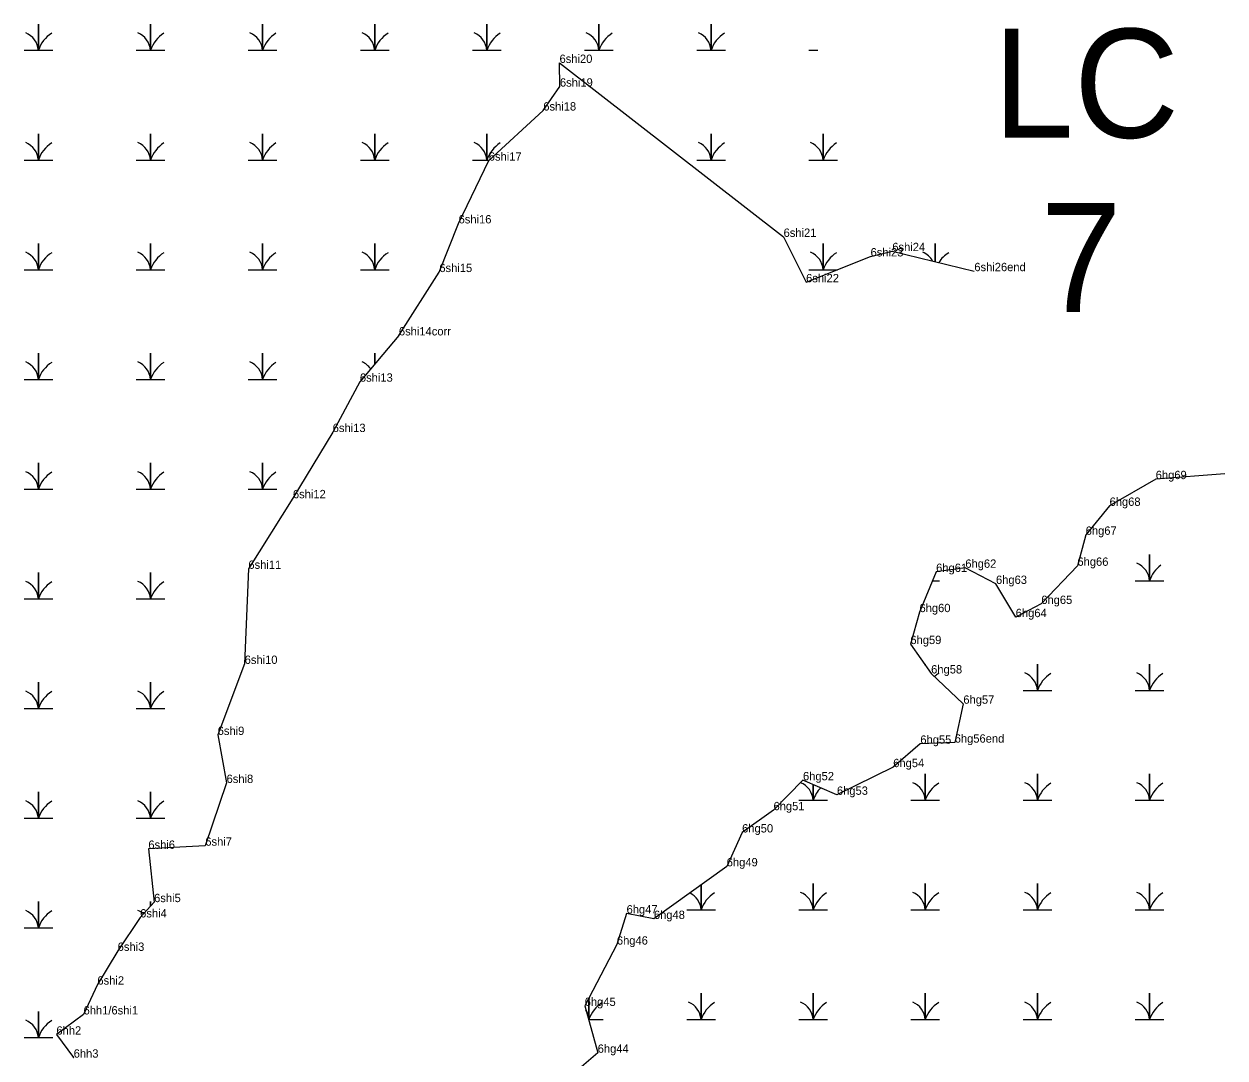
# Model space of a CAD drawing. Extents: x 2072529 to 2268796, y 436423 to 470406.
# Drawn here: x 2148024 to 2148744, y 442728 to 443348 of the extents above; entities that cross this region are included whole.
import ezdxf

# ---------------------------------------------------------------- set-up
doc = ezdxf.new("R2010")
doc.units = 0
for name, color, linetype in [('Default', 7, 'Continuous'), ('Exist Environmental Wetland Boundary Cogo Comment', 7, 'Continuous'), ('Exist Environmental Wetland Boundary Cogo Point CELL', 7, 'Continuous'), ('Exist Hydro Jurisdictional Stream or Body of Water NEU Mitigable Cogo Comment', 7, 'Continuous'), ('Old_Level_20', 7, 'Continuous'), ('Old_Level_52', 7, 'Continuous')]:
    doc.layers.add(name, color=color, linetype=linetype)

msp = doc.modelspace()

# ---------------------------------------------------------------- linework, layer by layer
at = {"layer": 'Exist Environmental Wetland Boundary Cogo Point CELL'}
for points in [[(2148023.58, 443332.03), (2148032.18, 443332.03), (2148032.18, 443347.81), (2148032.18, 443332.03), (2148040.78, 443332.03)], [(2148090.83, 443332.03), (2148099.43, 443332.03), (2148099.43, 443347.81), (2148099.43, 443332.03), (2148108.03, 443332.03)], [(2148158.08, 443332.03), (2148166.68, 443332.03), (2148166.68, 443347.81), (2148166.68, 443332.03), (2148175.28, 443332.03)], [(2148225.33, 443332.03), (2148233.93, 443332.03), (2148233.93, 443347.81), (2148233.93, 443332.03), (2148242.53, 443332.03)], [(2148292.58, 443332.03), (2148301.18, 443332.03), (2148301.18, 443347.81), (2148301.18, 443332.03), (2148309.78, 443332.03)], [(2148359.83, 443332.03), (2148368.43, 443332.03), (2148368.43, 443347.81), (2148368.43, 443332.03), (2148377.03, 443332.03)], [(2148427.08, 443332.03), (2148435.68, 443332.03), (2148435.68, 443347.81), (2148435.68, 443332.03), (2148444.28, 443332.03)], [(2148494.33, 443332.03), (2148499.78, 443332.03)], [(2148023.58, 443266.23), (2148032.18, 443266.23), (2148032.18, 443282.01), (2148032.18, 443266.23), (2148040.78, 443266.23)], [(2148090.83, 443266.23), (2148099.43, 443266.23), (2148099.43, 443282.01), (2148099.43, 443266.23), (2148108.03, 443266.23)], [(2148158.08, 443266.23), (2148166.68, 443266.23), (2148166.68, 443282.01), (2148166.68, 443266.23), (2148175.28, 443266.23)], [(2148225.33, 443266.23), (2148233.93, 443266.23), (2148233.93, 443282.01), (2148233.93, 443266.23), (2148242.53, 443266.23)], [(2148292.58, 443266.23), (2148301.18, 443266.23), (2148301.18, 443282.01), (2148301.18, 443266.23), (2148302.75, 443266.23)], [(2148427.08, 443266.23), (2148435.68, 443266.23), (2148435.68, 443282.01), (2148435.68, 443266.23), (2148444.28, 443266.23)], [(2148494.33, 443266.23), (2148502.93, 443266.23), (2148502.93, 443282.01), (2148502.93, 443266.23), (2148511.53, 443266.23)], [(2148023.58, 443200.43), (2148032.18, 443200.43), (2148032.18, 443216.21), (2148032.18, 443200.43), (2148040.78, 443200.43)], [(2148090.83, 443200.43), (2148099.43, 443200.43), (2148099.43, 443216.21), (2148099.43, 443200.43), (2148108.03, 443200.43)], [(2148158.08, 443200.43), (2148166.68, 443200.43), (2148166.68, 443216.21), (2148166.68, 443200.43), (2148175.28, 443200.43)], [(2148225.33, 443200.43), (2148233.93, 443200.43), (2148233.93, 443216.21), (2148233.93, 443200.43), (2148242.53, 443200.43)], [(2148494.33, 443200.43), (2148502.93, 443200.43), (2148502.93, 443216.21), (2148502.93, 443200.43), (2148511.47, 443200.43)], [(2148570.18, 443205.29), (2148570.18, 443216.21), (2148570.18, 443205.29)], [(2148023.58, 443134.63), (2148032.18, 443134.63), (2148032.18, 443150.41), (2148032.18, 443134.63), (2148040.78, 443134.63)], [(2148090.83, 443134.63), (2148099.43, 443134.63), (2148099.43, 443150.41), (2148099.43, 443134.63), (2148108.03, 443134.63)], [(2148158.08, 443134.63), (2148166.68, 443134.63), (2148166.68, 443150.41), (2148166.68, 443134.63), (2148175.28, 443134.63)], [(2148233.93, 443143.8), (2148233.93, 443150.41), (2148233.93, 443143.8)], [(2148225.33, 443134.63), (2148226.2, 443134.63)], [(2148023.58, 443068.83), (2148032.18, 443068.83), (2148032.18, 443084.61), (2148032.18, 443068.83), (2148040.78, 443068.83)], [(2148090.83, 443068.83), (2148099.43, 443068.83), (2148099.43, 443084.61), (2148099.43, 443068.83), (2148108.03, 443068.83)], [(2148158.08, 443068.83), (2148166.68, 443068.83), (2148166.68, 443084.61), (2148166.68, 443068.83), (2148175.28, 443068.83)], [(2148690.09, 443013.88), (2148698.69, 443013.88), (2148698.69, 443029.66), (2148698.69, 443013.88), (2148707.29, 443013.88)], [(2148023.58, 443003.03), (2148032.18, 443003.03), (2148032.18, 443018.81), (2148032.18, 443003.03), (2148040.78, 443003.03)], [(2148090.83, 443003.03), (2148099.43, 443003.03), (2148099.43, 443018.81), (2148099.43, 443003.03), (2148108.03, 443003.03)], [(2148568.5, 443013.88), (2148572.79, 443013.88)], [(2148564.19, 442963.22), (2148564.19, 442963.86), (2148564.19, 442963.22)], [(2148622.84, 442948.08), (2148631.44, 442948.08), (2148631.44, 442963.86), (2148631.44, 442948.08), (2148640.04, 442948.08)], [(2148690.09, 442948.08), (2148698.69, 442948.08), (2148698.69, 442963.86), (2148698.69, 442948.08), (2148707.29, 442948.08)], [(2148023.58, 442937.23), (2148032.18, 442937.23), (2148032.18, 442953.01), (2148032.18, 442937.23), (2148040.78, 442937.23)], [(2148090.83, 442937.23), (2148099.43, 442937.23), (2148099.43, 442953.01), (2148099.43, 442937.23), (2148108.03, 442937.23)], [(2148555.59, 442882.28), (2148564.19, 442882.28), (2148564.19, 442898.06), (2148564.19, 442882.28), (2148572.79, 442882.28)], [(2148622.84, 442882.28), (2148631.44, 442882.28), (2148631.44, 442898.06), (2148631.44, 442882.28), (2148640.04, 442882.28)], [(2148690.09, 442882.28), (2148698.69, 442882.28), (2148698.69, 442898.06), (2148698.69, 442882.28), (2148707.29, 442882.28)], [(2148023.58, 442871.43), (2148032.18, 442871.43), (2148032.18, 442887.21), (2148032.18, 442871.43), (2148040.78, 442871.43)], [(2148090.83, 442871.43), (2148099.43, 442871.43), (2148099.43, 442887.21), (2148099.43, 442871.43), (2148108.03, 442871.43)], [(2148488.34, 442882.28), (2148496.94, 442882.28), (2148496.94, 442891.57)], [(2148496.94, 442891.57), (2148496.94, 442882.28), (2148505.54, 442882.28)], [(2148421.09, 442816.48), (2148429.69, 442816.48), (2148429.69, 442831.47)], [(2148429.69, 442831.47), (2148429.69, 442816.48), (2148438.29, 442816.48)], [(2148488.34, 442816.48), (2148496.94, 442816.48), (2148496.94, 442832.26), (2148496.94, 442816.48), (2148505.54, 442816.48)], [(2148555.59, 442816.48), (2148564.19, 442816.48), (2148564.19, 442832.26), (2148564.19, 442816.48), (2148572.79, 442816.48)], [(2148622.84, 442816.48), (2148631.44, 442816.48), (2148631.44, 442832.26), (2148631.44, 442816.48), (2148640.04, 442816.48)], [(2148690.09, 442816.48), (2148698.69, 442816.48), (2148698.69, 442832.26), (2148698.69, 442816.48), (2148707.29, 442816.48)], [(2148023.58, 442805.63), (2148032.18, 442805.63), (2148032.18, 442821.41), (2148032.18, 442805.63), (2148040.78, 442805.63)], [(2148099.43, 442818.71), (2148099.43, 442821.41), (2148099.43, 442818.71)], [(2148362.15, 442750.68), (2148362.44, 442750.68), (2148362.44, 442763.72)], [(2148362.44, 442763.72), (2148362.44, 442750.68), (2148371.04, 442750.68)], [(2148421.09, 442750.68), (2148429.69, 442750.68), (2148429.69, 442766.46), (2148429.69, 442750.68), (2148438.29, 442750.68)], [(2148488.34, 442750.68), (2148496.94, 442750.68), (2148496.94, 442766.46), (2148496.94, 442750.68), (2148505.54, 442750.68)], [(2148555.59, 442750.68), (2148564.19, 442750.68), (2148564.19, 442766.46), (2148564.19, 442750.68), (2148572.79, 442750.68)], [(2148622.84, 442750.68), (2148631.44, 442750.68), (2148631.44, 442766.46), (2148631.44, 442750.68), (2148640.04, 442750.68)], [(2148690.09, 442750.68), (2148698.69, 442750.68), (2148698.69, 442766.46), (2148698.69, 442750.68), (2148707.29, 442750.68)], [(2148023.58, 442739.83), (2148032.18, 442739.83), (2148032.18, 442755.61), (2148032.18, 442739.83), (2148040.78, 442739.83)]]:
    msp.add_lwpolyline(points, dxfattribs=at)
for centre, radius, start, end in [((2148019.91, 443331.14), 12.3, 4.14034, 67.53497), ((2148050.42, 443325.97), 19.22, 122.12745, 161.62219), ((2148087.16, 443331.14), 12.3, 4.14034, 67.53497), ((2148117.67, 443325.97), 19.22, 122.12745, 161.62219), ((2148154.41, 443331.14), 12.3, 4.14034, 67.53497), ((2148184.92, 443325.97), 19.22, 122.12745, 161.62219), ((2148221.66, 443331.14), 12.3, 4.14034, 67.53497), ((2148252.17, 443325.97), 19.22, 122.12745, 161.62219), ((2148288.91, 443331.14), 12.3, 4.14034, 67.53497), ((2148319.42, 443325.97), 19.22, 122.12745, 161.62219), ((2148356.16, 443331.14), 12.3, 4.14034, 67.53497), ((2148386.67, 443325.97), 19.22, 122.12745, 161.62219), ((2148423.41, 443331.14), 12.3, 4.14034, 67.53497), ((2148453.92, 443325.97), 19.22, 122.12745, 161.62219), ((2148019.91, 443265.34), 12.3, 4.14034, 67.53497), ((2148050.42, 443260.17), 19.22, 122.12745, 161.62219), ((2148087.16, 443265.34), 12.3, 4.14034, 67.53497), ((2148117.67, 443260.17), 19.22, 122.12745, 161.62219), ((2148154.41, 443265.34), 12.3, 4.14034, 67.53497), ((2148184.92, 443260.17), 19.22, 122.12745, 161.62219), ((2148221.66, 443265.34), 12.3, 4.14034, 67.53497), ((2148252.17, 443260.17), 19.22, 122.12745, 161.62219), ((2148288.91, 443265.34), 12.3, 4.14034, 67.53497), ((2148319.42, 443260.17), 19.22, 122.12745, 161.62219), ((2148423.41, 443265.34), 12.3, 4.14034, 67.53497), ((2148453.92, 443260.17), 19.22, 122.12745, 161.62219), ((2148490.66, 443265.34), 12.3, 4.14034, 67.53497), ((2148521.17, 443260.17), 19.22, 122.12745, 161.62219), ((2148019.91, 443199.54), 12.3, 4.14034, 67.53497), ((2148050.42, 443194.37), 19.22, 122.12745, 161.62219), ((2148087.16, 443199.54), 12.3, 4.14034, 67.53497), ((2148117.67, 443194.37), 19.22, 122.12745, 161.62219), ((2148154.41, 443199.54), 12.3, 4.14034, 67.53497), ((2148184.92, 443194.37), 19.22, 122.12745, 161.62219), ((2148221.66, 443199.54), 12.3, 4.14034, 67.53497), ((2148252.17, 443194.37), 19.22, 122.12745, 161.62219), ((2148490.66, 443199.54), 12.3, 4.14034, 67.53497), ((2148521.17, 443194.37), 19.22, 122.12745, 161.62219), ((2148557.91, 443199.54), 12.3, 29.96373, 67.53497), ((2148588.42, 443194.37), 19.22, 122.12745, 147.20533), ((2148019.91, 443133.74), 12.3, 4.14034, 67.53497), ((2148050.42, 443128.57), 19.22, 122.12745, 161.62219), ((2148087.16, 443133.74), 12.3, 4.14034, 67.53497), ((2148117.67, 443128.57), 19.22, 122.12745, 161.62219), ((2148154.41, 443133.74), 12.3, 4.14034, 67.53497), ((2148184.92, 443128.57), 19.22, 122.12745, 161.62219), ((2148221.66, 443133.74), 12.3, 36.24182, 67.53497), ((2148019.91, 443067.94), 12.3, 4.14034, 67.53497), ((2148087.16, 443067.94), 12.3, 4.14034, 67.53497), ((2148154.41, 443067.94), 12.3, 4.14034, 67.53497), ((2148050.42, 443062.77), 19.22, 122.12745, 161.62219), ((2148117.67, 443062.77), 19.22, 122.12745, 161.62219), ((2148184.92, 443062.77), 19.22, 122.12745, 161.62219), ((2148686.42, 443013), 12.3, 4.14034, 67.53497), ((2148716.93, 443007.82), 19.22, 126.99875, 161.62219), ((2148019.91, 443002.14), 12.3, 4.14034, 67.53497), ((2148050.42, 442996.97), 19.22, 122.12745, 161.62219), ((2148087.16, 443002.14), 12.3, 4.14034, 67.53497), ((2148117.67, 442996.97), 19.22, 122.12745, 161.62219), ((2148582.43, 442942.02), 19.22, 122.12745, 131.59366), ((2148619.17, 442947.2), 12.3, 4.14034, 67.53497), ((2148649.68, 442942.02), 19.22, 122.12745, 161.62219), ((2148686.42, 442947.2), 12.3, 4.14034, 67.53497), ((2148716.93, 442942.02), 19.22, 122.12745, 161.62219), ((2148019.91, 442936.34), 12.3, 4.14034, 67.53497), ((2148050.42, 442931.17), 19.22, 122.12745, 161.62219), ((2148087.16, 442936.34), 12.3, 4.14034, 67.53497), ((2148117.67, 442931.17), 19.22, 122.12745, 161.62219), ((2148484.67, 442881.4), 12.3, 4.14034, 67.41991), ((2148551.92, 442881.4), 12.3, 4.14034, 67.53497), ((2148582.43, 442876.22), 19.22, 122.12745, 161.62219), ((2148619.17, 442881.4), 12.3, 4.14034, 67.53497), ((2148649.68, 442876.22), 19.22, 122.12745, 161.62219), ((2148686.42, 442881.4), 12.3, 4.14034, 67.53497), ((2148716.93, 442876.22), 19.22, 122.12745, 161.62219), ((2148515.18, 442876.22), 19.22, 135.67101, 161.62219), ((2148019.91, 442870.54), 12.3, 4.14034, 67.53497), ((2148050.42, 442865.37), 19.22, 122.12745, 161.62219), ((2148087.16, 442870.54), 12.3, 4.14034, 67.53497), ((2148117.67, 442865.37), 19.22, 122.12745, 161.62219), ((2148484.67, 442815.6), 12.3, 4.14034, 67.53497), ((2148551.92, 442815.6), 12.3, 4.14034, 67.53497), ((2148619.17, 442815.6), 12.3, 4.14034, 67.53497), ((2148686.42, 442815.6), 12.3, 4.14034, 67.53497), ((2148417.42, 442815.6), 12.3, 4.14034, 63.35338), ((2148447.93, 442810.42), 19.22, 122.12745, 161.62219), ((2148515.18, 442810.42), 19.22, 122.12745, 161.62219), ((2148582.43, 442810.42), 19.22, 122.12745, 161.62219), ((2148649.68, 442810.42), 19.22, 122.12745, 161.62219), ((2148716.93, 442810.42), 19.22, 122.12745, 161.62219), ((2148019.91, 442804.74), 12.3, 4.14034, 67.53497), ((2148050.42, 442799.57), 19.22, 122.12745, 161.62219), ((2148087.16, 442804.74), 12.3, 49.31719, 67.53497), ((2148350.17, 442749.8), 12.3, 4.14034, 32.20547), ((2148380.68, 442744.62), 19.22, 122.12745, 161.62219), ((2148417.42, 442749.8), 12.3, 4.14034, 67.53497), ((2148447.93, 442744.62), 19.22, 122.12745, 161.62219), ((2148484.67, 442749.8), 12.3, 4.14034, 67.53497), ((2148515.18, 442744.62), 19.22, 122.12745, 161.62219), ((2148551.92, 442749.8), 12.3, 4.14034, 67.53497), ((2148582.43, 442744.62), 19.22, 122.12745, 161.62219), ((2148619.17, 442749.8), 12.3, 4.14034, 67.53497), ((2148649.68, 442744.62), 19.22, 122.12745, 161.62219), ((2148686.42, 442749.8), 12.3, 4.14034, 67.53497), ((2148716.93, 442744.62), 19.22, 122.12745, 161.62219), ((2148019.91, 442738.94), 12.3, 4.14034, 67.53497), ((2148050.42, 442733.77), 19.22, 122.12745, 161.62219)]:
    msp.add_arc(centre, radius, start, end, dxfattribs=at)
at = {"layer": 'Old_Level_20'}
for p, q in [((2148344.78, 443324.48), (2148344.78, 443324.48)), ((2148345.03, 443310.25), (2148345.03, 443310.25)), ((2148335.04, 443295.91), (2148335.04, 443295.91)), ((2148302.36, 443265.87), (2148302.36, 443265.87)), ((2148284.24, 443228.21), (2148284.24, 443228.21)), ((2148531.35, 443208.41), (2148531.35, 443208.41)), ((2148272.69, 443199.03), (2148272.69, 443199.03)), ((2148593.41, 443199.74), (2148593.41, 443199.74)), ((2148248.44, 443161.02), (2148248.44, 443161.02)), ((2148248.44, 443161.02), (2148248.44, 443161.02)), ((2148248.44, 443161.02), (2148248.44, 443161.02)), ((2148225.05, 443133.27), (2148225.05, 443133.27)), ((2148225.05, 443133.27), (2148225.05, 443133.27)), ((2148225.05, 443133.27), (2148225.05, 443133.27)), ((2148208.74, 443103.08), (2148208.74, 443103.08)), ((2148208.74, 443103.08), (2148208.74, 443103.08)), ((2148208.74, 443103.08), (2148208.74, 443103.08)), ((2148702.4, 443074.83), (2148702.4, 443074.83)), ((2148743.94, 443077.93), (2148743.94, 443077.93)), ((2148184.87, 443063.36), (2148184.87, 443063.36)), ((2148184.87, 443063.36), (2148184.87, 443063.36)), ((2148184.87, 443063.36), (2148184.87, 443063.36)), ((2148674.71, 443058.8), (2148674.71, 443058.8)), ((2148660.38, 443041.45), (2148660.38, 443041.45)), ((2148588.18, 443021.66), (2148588.18, 443021.66)), ((2148655.43, 443022.84), (2148655.43, 443022.84)), ((2148158.16, 443021.01), (2148158.16, 443021.01)), ((2148158.16, 443021.01), (2148158.16, 443021.01)), ((2148158.16, 443021.01), (2148158.16, 443021.01)), ((2148570.68, 443019.16), (2148570.68, 443019.16)), ((2148606.58, 443011.97), (2148606.58, 443011.97)), ((2148633.74, 442999.95), (2148633.74, 442999.95)), ((2148560.71, 442995.05), (2148560.71, 442995.05)), ((2148618.42, 442992.05), (2148618.42, 442992.05)), ((2148555.23, 442975.9), (2148555.23, 442975.9)), ((2148155.92, 442964), (2148155.92, 442964)), ((2148155.92, 442964), (2148155.92, 442964)), ((2148155.92, 442964), (2148155.92, 442964)), ((2148567.69, 442958.26), (2148567.69, 442958.26)), ((2148586.99, 442940.11), (2148586.99, 442940.11)), ((2148139.74, 442921.38), (2148139.74, 442921.38)), ((2148139.74, 442921.38), (2148139.74, 442921.38)), ((2148139.74, 442921.38), (2148139.74, 442921.38)), ((2148561.2, 442916.12), (2148561.2, 442916.12)), ((2148561.2, 442916.12), (2148561.2, 442916.12)), ((2148581.81, 442916.78), (2148581.81, 442916.78)), ((2148581.81, 442916.78), (2148581.81, 442916.78)), ((2148544.94, 442902.08), (2148544.94, 442902.08)), ((2148544.94, 442902.08), (2148544.94, 442902.08)), ((2148145.08, 442892.59), (2148145.08, 442892.59)), ((2148145.08, 442892.59), (2148145.08, 442892.59)), ((2148145.08, 442892.59), (2148145.08, 442892.59)), ((2148490.81, 442894.19), (2148490.81, 442894.19)), ((2148490.81, 442894.19), (2148490.81, 442894.19)), ((2148511.18, 442885.49), (2148511.18, 442885.49)), ((2148511.18, 442885.49), (2148511.18, 442885.49)), ((2148473.14, 442876.23), (2148473.14, 442876.23)), ((2148473.14, 442876.23), (2148473.14, 442876.23)), ((2148454.31, 442862.89), (2148454.31, 442862.89)), ((2148454.31, 442862.89), (2148454.31, 442862.89)), ((2148098.17, 442853.08), (2148098.17, 442853.08)), ((2148098.17, 442853.08), (2148098.17, 442853.08)), ((2148098.17, 442853.08), (2148098.17, 442853.08)), ((2148132.31, 442854.95), (2148132.31, 442854.95)), ((2148132.31, 442854.95), (2148132.31, 442854.95)), ((2148132.31, 442854.95), (2148132.31, 442854.95)), ((2148445.08, 442842.58), (2148445.08, 442842.58)), ((2148445.08, 442842.58), (2148445.08, 442842.58)), ((2148101.62, 442821.11), (2148101.62, 442821.11)), ((2148101.62, 442821.11), (2148101.62, 442821.11)), ((2148101.62, 442821.11), (2148101.62, 442821.11)), ((2148384.99, 442814.3), (2148384.99, 442814.3)), ((2148384.99, 442814.3), (2148384.99, 442814.3)), ((2148093.23, 442811.94), (2148093.23, 442811.94)), ((2148093.23, 442811.94), (2148093.23, 442811.94)), ((2148093.23, 442811.94), (2148093.23, 442811.94)), ((2148401.4, 442811.02), (2148401.4, 442811.02)), ((2148401.4, 442811.02), (2148401.4, 442811.02)), ((2148079.75, 442791.88), (2148079.75, 442791.88)), ((2148079.75, 442791.88), (2148079.75, 442791.88)), ((2148079.75, 442791.88), (2148079.75, 442791.88)), ((2148379.18, 442795.63), (2148379.18, 442795.63)), ((2148379.18, 442795.63), (2148379.18, 442795.63)), ((2148067.6, 442771.65), (2148067.6, 442771.65)), ((2148067.6, 442771.65), (2148067.6, 442771.65)), ((2148067.6, 442771.65), (2148067.6, 442771.65)), ((2148359.89, 442758.85), (2148359.89, 442758.85)), ((2148359.89, 442758.85), (2148359.89, 442758.85)), ((2148059.29, 442753.74), (2148059.29, 442753.74)), ((2148043.01, 442741.65), (2148043.01, 442741.65)), ((2148053.35, 442727.83), (2148053.35, 442727.83)), ((2148367.67, 442730.75), (2148367.67, 442730.75)), ((2148367.67, 442730.75), (2148367.67, 442730.75))]:
    msp.add_line(p, q, dxfattribs=at)
for points in [[(2148743.94, 443077.93), (2148702.4, 443074.83), (2148674.71, 443058.8), (2148660.38, 443041.45), (2148655.43, 443022.84), (2148633.74, 442999.95), (2148618.42, 442992.05), (2148606.58, 443011.97), (2148588.18, 443021.66), (2148570.68, 443019.16)], [(2148570.68, 443019.16), (2148560.71, 442995.05), (2148555.23, 442975.9), (2148567.69, 442958.26), (2148586.99, 442940.11), (2148581.81, 442916.78), (2148561.2, 442916.12), (2148544.94, 442902.08), (2148511.18, 442885.49), (2148490.81, 442894.19), (2148473.14, 442876.23), (2148454.31, 442862.89), (2148445.08, 442842.58)], [(2148445.08, 442842.58), (2148401.4, 442811.02), (2148384.99, 442814.3), (2148379.18, 442795.63), (2148359.89, 442758.85), (2148367.67, 442730.75), (2148350.88, 442716.4)], [(2148059.29, 442753.74), (2148043.01, 442741.65), (2148053.23, 442727.98)]]:
    msp.add_lwpolyline(points, dxfattribs=at)
msp.add_arc((2148052.43, 442727.38), 1, 14.73756, 36.80018, dxfattribs=at)
at = {"layer": 'Old_Level_52'}
for points in [[(2148248.44, 443161.02), (2148272.69, 443199.03), (2148284.24, 443228.21), (2148302.36, 443265.87), (2148335.04, 443295.91), (2148345.03, 443310.25), (2148344.78, 443324.48)], [(2148344.78, 443324.48), (2148479.17, 443220.14), (2148492.69, 443192.9), (2148531.35, 443208.41), (2148544.39, 443211.6), (2148593.58, 443199.57)], [(2148248.44, 443161.02), (2148225.05, 443133.27), (2148208.74, 443103.08), (2148184.87, 443063.36), (2148158.16, 443021.01), (2148155.92, 442964), (2148139.74, 442921.38), (2148145.08, 442892.59), (2148132.31, 442854.95), (2148098.17, 442853.08), (2148101.62, 442821.11), (2148093.23, 442811.94), (2148079.75, 442791.88), (2148067.6, 442771.65), (2148059.29, 442753.74)]]:
    msp.add_lwpolyline(points, dxfattribs=at)

# ---------------------------------------------------------------- texts
at = {"layer": 'Default'}
for s, p in [('LC', (2148604.74, 443279.6)), ('7', (2148633.33, 443175.05))]:
    msp.add_text(s, height=65.34, dxfattribs=at).set_placement(p)
at = {"layer": 'Exist Environmental Wetland Boundary Cogo Comment'}
for s, p in [('6hg69', (2148702.4, 443074.83)), ('6hg68', (2148674.71, 443058.8)), ('6hg67', (2148660.38, 443041.45)), ('6hg61', (2148570.68, 443019.16)), ('6hg62', (2148588.18, 443021.66)), ('6hg66', (2148655.43, 443022.84)), ('6hg63', (2148606.58, 443011.97)), ('6hg60', (2148560.71, 442995.05)), ('6hg65', (2148633.74, 442999.95)), ('6hg64', (2148618.42, 442992.05)), ('6hg59', (2148555.23, 442975.9)), ('6hg58', (2148567.69, 442958.26)), ('6hg57', (2148586.99, 442940.11)), ('6hg55', (2148561.2, 442916.12)), ('6hg56end', (2148581.81, 442916.78)), ('6hg56', (2148581.81, 442916.78)), ('6hg54', (2148544.94, 442902.08)), ('6hg52', (2148490.81, 442894.19)), ('6hg53', (2148511.18, 442885.49)), ('6hg51', (2148473.14, 442876.23)), ('6hg50', (2148454.31, 442862.89)), ('6hg49', (2148445.08, 442842.58)), ('6hg47', (2148384.99, 442814.3)), ('6hg48', (2148401.4, 442811.02)), ('6hg46', (2148379.18, 442795.63)), ('6hg45', (2148359.89, 442758.85)), ('6hh2', (2148043.01, 442741.65)), ('6hg44', (2148367.67, 442730.75)), ('6hh3', (2148053.35, 442727.83))]:
    msp.add_text(s, height=5, dxfattribs=at).set_placement(p)
at = {"layer": 'Exist Hydro Jurisdictional Stream or Body of Water NEU Mitigable Cogo Comment'}
for s, p in [('6shi20', (2148344.78, 443324.48)), ('6shi19', (2148345.03, 443310.25)), ('6shi18', (2148335.04, 443295.91)), ('6shi17', (2148302.36, 443265.87)), ('6shi16', (2148284.24, 443228.21)), ('6shi21', (2148479.17, 443220.14)), ('6shi24', (2148544.39, 443211.6)), ('6shi23', (2148531.35, 443208.41)), ('6shi15', (2148272.69, 443199.03)), ('6shi26end', (2148593.58, 443199.57)), ('6shi22', (2148492.69, 443192.9)), ('6shi14corr', (2148248.44, 443161.02)), ('6shi14', (2148248.44, 443161.02)), ('6shi13', (2148225.05, 443133.27)), ('6shi13', (2148208.74, 443103.08)), ('6shi12', (2148184.87, 443063.36)), ('6shi11', (2148158.16, 443021.01)), ('6shi10', (2148155.92, 442964)), ('6shi9', (2148139.74, 442921.38)), ('6shi8', (2148145.08, 442892.59)), ('6shi6', (2148098.17, 442853.08)), ('6shi7', (2148132.31, 442854.95)), ('6shi5', (2148101.62, 442821.11)), ('6shi4', (2148093.23, 442811.94)), ('6shi3', (2148079.75, 442791.88)), ('6shi2', (2148067.6, 442771.65)), ('6hh1/6shi1', (2148059.29, 442753.74))]:
    msp.add_text(s, height=5, dxfattribs=at).set_placement(p)

doc.saveas('drawing.dxf')
